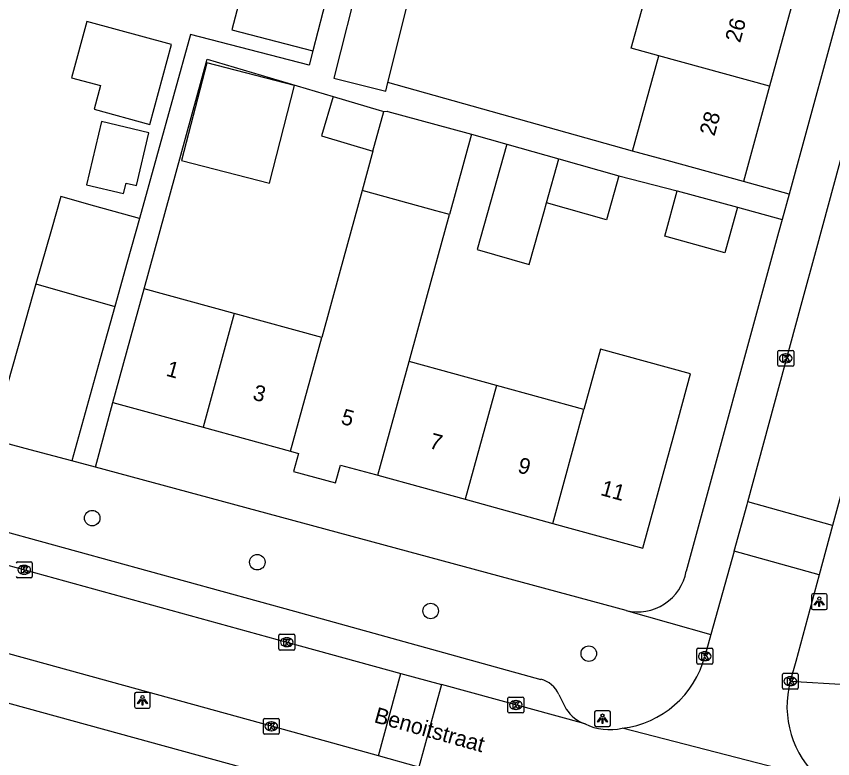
# Model space of a CAD drawing. Extents: x 159822 to 160765, y 380693 to 381634.
# Drawn here: x 160250.2 to 160301.9, y 381019.2 to 381066.1 of the extents above; entities that cross this region are included whole.
import ezdxf

# ---------------------------------------------------------------- set-up
doc = ezdxf.new("R2010")
doc.units = 0
for name, color, linetype in [('IMGEO_Boom', 7, 'Continuous'), ('IMGEO_Kolk', 7, 'Continuous'), ('IMGEO_Lichtpunt', 7, 'Continuous'), ('IMGEO_Openbare_ruimte_label', 7, 'Continuous'), ('IMGEO_Pand', 7, 'Continuous'), ('IMGEO_Pand_nummerreeks', 7, 'Continuous'), ('IMGEO_Rijbaan_lokaal_open', 7, 'Continuous'), ('IMGEO_Voetpad_open', 7, 'Continuous')]:
    doc.layers.add(name, color=color, linetype=linetype)

msp = doc.modelspace()

# ---------------------------------------------------------------- linework, layer by layer
at = {"layer": 'IMGEO_Boom'}
for centre in [(160255.039, 381034.397), (160265.483, 381031.606), (160276.45, 381028.521), (160286.454, 381025.822)]:
    msp.add_circle(centre, 0.489, dxfattribs=at)
at = {"layer": 'IMGEO_Kolk'}
for p, q in [((160298.416, 381044.081), (160298.416, 381044.933)), ((160298.491, 381045.007), (160299.343, 381045.007)), ((160298.904, 381044.787), (160298.929, 381044.787)), ((160299.417, 381044.933), (160299.417, 381044.081)), ((160298.927, 381044.227), (160298.902, 381044.227)), ((160299.343, 381044.007), (160298.491, 381044.007)), ((160250.311, 381031.625), (160251.163, 381031.625)), ((160250.724, 381031.405), (160250.749, 381031.405)), ((160251.237, 381031.551), (160251.237, 381030.699)), ((160250.747, 381030.845), (160250.722, 381030.845)), ((160251.163, 381030.625), (160250.311, 381030.625)), ((160266.849, 381026.121), (160266.849, 381026.973)), ((160266.924, 381027.047), (160267.776, 381027.047)), ((160267.337, 381026.827), (160267.362, 381026.827)), ((160267.85, 381026.973), (160267.85, 381026.121)), ((160267.36, 381026.267), (160267.335, 381026.267)), ((160293.293, 381025.233), (160293.293, 381026.085)), ((160293.368, 381026.159), (160294.22, 381026.159)), ((160294.294, 381026.085), (160294.294, 381025.233)), ((160267.776, 381026.047), (160266.924, 381026.047)), ((160293.781, 381025.939), (160293.806, 381025.939)), ((160294.22, 381025.159), (160293.368, 381025.159)), ((160293.804, 381025.379), (160293.779, 381025.379)), ((160298.779, 381024.577), (160299.631, 381024.577)), ((160298.704, 381023.651), (160298.704, 381024.503)), ((160299.192, 381024.357), (160299.217, 381024.357)), ((160299.705, 381024.503), (160299.705, 381023.651)), ((160299.631, 381023.577), (160298.779, 381023.577)), ((160299.215, 381023.797), (160299.19, 381023.797)), ((160281.339, 381022.15), (160281.339, 381023.002)), ((160281.414, 381023.076), (160282.266, 381023.076)), ((160282.34, 381023.002), (160282.34, 381022.15)), ((160281.827, 381022.856), (160281.852, 381022.856)), ((160282.266, 381022.076), (160281.414, 381022.076)), ((160281.85, 381022.296), (160281.825, 381022.296)), ((160265.867, 381020.8), (160265.867, 381021.652)), ((160265.942, 381021.726), (160266.794, 381021.726)), ((160266.355, 381021.506), (160266.38, 381021.506)), ((160266.868, 381021.652), (160266.868, 381020.8)), ((160266.378, 381020.946), (160266.353, 381020.946)), ((160266.794, 381020.726), (160265.942, 381020.726))]:
    msp.add_line(p, q, dxfattribs=at)
for points in [[(160298.416, 381044.081), (160298.416, 381044.933)], [(160298.491, 381045.007), (160299.343, 381045.007)], [(160298.737, 381044.707), (160298.86, 381044.707), (160298.86, 381044.556), (160298.99, 381044.707), (160299.154, 381044.707), (160299.008, 381044.556), (160299.161, 381044.307), (160299.009, 381044.307), (160298.924, 381044.471), (160298.86, 381044.404), (160298.86, 381044.307), (160298.737, 381044.307), (160298.737, 381044.707)], [(160299.417, 381044.933), (160299.417, 381044.081)], [(160299.343, 381044.007), (160298.491, 381044.007)], [(160250.311, 381031.625), (160251.163, 381031.625)], [(160250.557, 381031.325), (160250.68, 381031.325), (160250.68, 381031.174), (160250.81, 381031.325), (160250.974, 381031.325), (160250.828, 381031.174), (160250.981, 381030.925), (160250.829, 381030.925), (160250.744, 381031.089), (160250.68, 381031.022), (160250.68, 381030.925), (160250.557, 381030.925), (160250.557, 381031.325)], [(160251.237, 381031.551), (160251.237, 381030.699)], [(160251.163, 381030.625), (160250.311, 381030.625)], [(160266.849, 381026.121), (160266.849, 381026.973)], [(160266.924, 381027.047), (160267.776, 381027.047)], [(160267.17, 381026.747), (160267.293, 381026.747), (160267.293, 381026.596), (160267.423, 381026.747), (160267.587, 381026.747), (160267.441, 381026.596), (160267.594, 381026.347), (160267.442, 381026.347), (160267.357, 381026.511), (160267.293, 381026.444), (160267.293, 381026.347), (160267.17, 381026.347), (160267.17, 381026.747)], [(160267.85, 381026.973), (160267.85, 381026.121)], [(160293.293, 381025.233), (160293.293, 381026.085)], [(160293.368, 381026.159), (160294.22, 381026.159)], [(160294.294, 381026.085), (160294.294, 381025.233)], [(160267.776, 381026.047), (160266.924, 381026.047)], [(160293.614, 381025.859), (160293.737, 381025.859), (160293.737, 381025.708), (160293.867, 381025.859), (160294.031, 381025.859), (160293.885, 381025.708), (160294.038, 381025.459), (160293.886, 381025.459), (160293.801, 381025.623), (160293.737, 381025.556), (160293.737, 381025.459), (160293.614, 381025.459), (160293.614, 381025.859)], [(160294.22, 381025.159), (160293.368, 381025.159)], [(160298.779, 381024.577), (160299.631, 381024.577)], [(160298.704, 381023.651), (160298.704, 381024.503)], [(160299.025, 381024.277), (160299.148, 381024.277), (160299.148, 381024.126), (160299.278, 381024.277), (160299.442, 381024.277), (160299.296, 381024.126), (160299.449, 381023.877), (160299.297, 381023.877), (160299.212, 381024.041), (160299.148, 381023.974), (160299.148, 381023.877), (160299.025, 381023.877), (160299.025, 381024.277)], [(160299.705, 381024.503), (160299.705, 381023.651)], [(160299.631, 381023.577), (160298.779, 381023.577)], [(160281.339, 381022.15), (160281.339, 381023.002)], [(160281.414, 381023.076), (160282.266, 381023.076)], [(160282.34, 381023.002), (160282.34, 381022.15)], [(160281.66, 381022.776), (160281.783, 381022.776), (160281.783, 381022.625), (160281.913, 381022.776), (160282.077, 381022.776), (160281.931, 381022.625), (160282.084, 381022.376), (160281.932, 381022.376), (160281.847, 381022.54), (160281.783, 381022.473), (160281.783, 381022.376), (160281.66, 381022.376), (160281.66, 381022.776)], [(160282.266, 381022.076), (160281.414, 381022.076)], [(160265.867, 381020.8), (160265.867, 381021.652)], [(160265.942, 381021.726), (160266.794, 381021.726)], [(160266.868, 381021.652), (160266.868, 381020.8)], [(160266.188, 381021.426), (160266.311, 381021.426), (160266.311, 381021.275), (160266.441, 381021.426), (160266.605, 381021.426), (160266.459, 381021.275), (160266.612, 381021.026), (160266.46, 381021.026), (160266.375, 381021.19), (160266.311, 381021.123), (160266.311, 381021.026), (160266.188, 381021.026), (160266.188, 381021.426)], [(160266.794, 381020.726), (160265.942, 381020.726)]]:
    msp.add_lwpolyline(points, dxfattribs=at)
for centre, start, end in [((160298.493, 381044.931), 91.552, 178.448), ((160298.493, 381044.931), 91.552, 178.448), ((160299.341, 381044.931), 1.552, 88.448), ((160299.341, 381044.931), 1.552, 88.448), ((160298.493, 381044.083), 181.552, 268.448), ((160298.493, 381044.083), 181.552, 268.448), ((160299.341, 381044.083), 271.552, 358.448), ((160299.341, 381044.083), 271.552, 358.448), ((160250.313, 381031.549), 91.552, 178.448), ((160250.313, 381031.549), 91.552, 178.448), ((160251.161, 381031.549), 1.552, 88.448), ((160251.161, 381031.549), 1.552, 88.448), ((160250.313, 381030.701), 181.552, 268.448), ((160250.313, 381030.701), 181.552, 268.448), ((160251.161, 381030.701), 271.552, 358.448), ((160251.161, 381030.701), 271.552, 358.448), ((160266.926, 381026.971), 91.552, 178.448), ((160266.926, 381026.971), 91.552, 178.448), ((160267.774, 381026.971), 1.552, 88.448), ((160267.774, 381026.971), 1.552, 88.448), ((160266.926, 381026.123), 181.552, 268.448), ((160266.926, 381026.123), 181.552, 268.448), ((160267.774, 381026.123), 271.552, 358.448), ((160267.774, 381026.123), 271.552, 358.448), ((160293.37, 381026.083), 91.552, 178.448), ((160293.37, 381026.083), 91.552, 178.448), ((160294.218, 381026.083), 1.552, 88.448), ((160294.218, 381026.083), 1.552, 88.448), ((160293.37, 381025.235), 181.552, 268.448), ((160293.37, 381025.235), 181.552, 268.448), ((160294.218, 381025.235), 271.552, 358.448), ((160294.218, 381025.235), 271.552, 358.448), ((160298.781, 381024.501), 91.552, 178.448), ((160298.781, 381024.501), 91.552, 178.448), ((160299.629, 381024.501), 1.552, 88.448), ((160299.629, 381024.501), 1.552, 88.448), ((160298.781, 381023.653), 181.552, 268.448), ((160298.781, 381023.653), 181.552, 268.448), ((160299.629, 381023.653), 271.552, 358.448), ((160299.629, 381023.653), 271.552, 358.448), ((160281.416, 381023), 91.552, 178.448), ((160281.416, 381023), 91.552, 178.448), ((160282.264, 381023), 1.552, 88.448), ((160282.264, 381023), 1.552, 88.448), ((160281.416, 381022.152), 181.552, 268.448), ((160281.416, 381022.152), 181.552, 268.448), ((160282.264, 381022.152), 271.552, 358.448), ((160282.264, 381022.152), 271.552, 358.448), ((160265.944, 381021.65), 91.552, 178.448), ((160265.944, 381021.65), 91.552, 178.448), ((160266.792, 381021.65), 1.552, 88.448), ((160266.792, 381021.65), 1.552, 88.448), ((160265.944, 381020.802), 181.552, 268.448), ((160265.944, 381020.802), 181.552, 268.448), ((160266.792, 381020.802), 271.552, 358.448), ((160266.792, 381020.802), 271.552, 358.448)]:
    msp.add_arc(centre, 0.0765, start, end, dxfattribs=at)
for centre, major_axis, ratio, start_param, end_param in [((160298.903, 381044.507), (-0.387, 0.002), 0.722429, 4.712389, 7.853982), ((160298.928, 381044.507), (-0.39, 0.002), 0.717154, 1.570796, 4.712389), ((160250.723, 381031.125), (-0.387, 0.002), 0.722429, 4.712389, 7.853982), ((160250.748, 381031.125), (-0.39, 0.002), 0.717154, 1.570796, 4.712389), ((160267.336, 381026.547), (-0.387, 0.002), 0.722429, 4.712389, 7.853982), ((160267.361, 381026.547), (-0.39, 0.002), 0.717154, 1.570796, 4.712389), ((160293.78, 381025.659), (-0.387, 0.002), 0.722429, 4.712389, 7.853982), ((160293.805, 381025.659), (-0.39, 0.002), 0.717154, 1.570796, 4.712389), ((160299.191, 381024.077), (-0.387, 0.002), 0.722429, 4.712389, 7.853982), ((160299.216, 381024.077), (-0.39, 0.002), 0.717154, 1.570796, 4.712389), ((160281.826, 381022.576), (-0.387, 0.002), 0.722429, 4.712389, 7.853982), ((160281.851, 381022.576), (-0.39, 0.002), 0.717154, 1.570796, 4.712389), ((160266.354, 381021.226), (-0.387, 0.002), 0.722429, 4.712389, 7.853982), ((160266.379, 381021.226), (-0.39, 0.002), 0.717154, 1.570796, 4.712389)]:
    msp.add_ellipse(centre, major_axis=major_axis, ratio=ratio, start_param=start_param, end_param=end_param, dxfattribs=at)
at = {"layer": 'IMGEO_Lichtpunt'}
for p, q in [((160300.536, 381029.509), (160300.536, 381028.702)), ((160300.536, 381029.509), (160300.536, 381028.702)), ((160301.438, 381029.604), (160300.63, 381029.604)), ((160301.438, 381029.604), (160300.63, 381029.604)), ((160301.532, 381028.702), (160301.532, 381029.509)), ((160301.532, 381028.702), (160301.532, 381029.509)), ((160300.63, 381028.608), (160301.438, 381028.608)), ((160300.63, 381028.608), (160301.438, 381028.608)), ((160257.718, 381023.276), (160257.718, 381022.469)), ((160257.718, 381023.276), (160257.718, 381022.469)), ((160258.62, 381023.371), (160257.812, 381023.371)), ((160258.62, 381023.371), (160257.812, 381023.371)), ((160258.714, 381022.469), (160258.714, 381023.276)), ((160258.714, 381022.469), (160258.714, 381023.276)), ((160257.812, 381022.375), (160258.62, 381022.375)), ((160257.812, 381022.375), (160258.62, 381022.375)), ((160286.825, 381022.112), (160286.825, 381021.305)), ((160286.825, 381022.112), (160286.825, 381021.305)), ((160287.727, 381022.207), (160286.919, 381022.207)), ((160287.727, 381022.207), (160286.919, 381022.207)), ((160287.821, 381021.305), (160287.821, 381022.112)), ((160287.821, 381021.305), (160287.821, 381022.112)), ((160286.919, 381021.211), (160287.727, 381021.211)), ((160286.919, 381021.211), (160287.727, 381021.211))]:
    msp.add_line(p, q, dxfattribs=at)
for points in [[(160300.91, 381029.173), (160300.949, 381029.145), (160300.761, 381028.883), (160300.723, 381028.91), (160300.91, 381029.173)], [(160301.012, 381029.125), (160301.059, 381029.125), (160301.059, 381028.803), (160301.012, 381028.803), (160301.012, 381029.125)], [(160301.122, 381029.145), (160301.16, 381029.172), (160301.347, 381028.91), (160301.308, 381028.882), (160301.122, 381029.145)], [(160258.092, 381022.94), (160258.131, 381022.912), (160257.943, 381022.65), (160257.905, 381022.677), (160258.092, 381022.94)], [(160258.194, 381022.892), (160258.241, 381022.892), (160258.241, 381022.57), (160258.194, 381022.57), (160258.194, 381022.892)], [(160258.304, 381022.912), (160258.342, 381022.939), (160258.529, 381022.677), (160258.49, 381022.649), (160258.304, 381022.912)], [(160287.199, 381021.776), (160287.238, 381021.748), (160287.05, 381021.486), (160287.012, 381021.513), (160287.199, 381021.776)], [(160287.301, 381021.728), (160287.348, 381021.728), (160287.348, 381021.406), (160287.301, 381021.406), (160287.301, 381021.728)], [(160287.411, 381021.748), (160287.449, 381021.775), (160287.636, 381021.513), (160287.597, 381021.485), (160287.411, 381021.748)]]:
    msp.add_lwpolyline(points, dxfattribs=at)
for centre in [(160301.035, 381029.307), (160258.217, 381023.074), (160287.324, 381021.91)]:
    msp.add_circle(centre, 0.0994, dxfattribs=at)
for centre, start, end in [((160300.63, 381029.509), 90, 180), ((160300.63, 381029.509), 90, 180), ((160301.438, 381029.509), 0, 90), ((160301.438, 381029.509), 0, 90), ((160300.63, 381028.702), 180, 270), ((160300.63, 381028.702), 180, 270), ((160301.438, 381028.702), 270, 0), ((160301.438, 381028.702), 270, 360), ((160257.812, 381023.276), 90, 180), ((160257.812, 381023.276), 90, 180), ((160258.62, 381023.276), 0, 90), ((160258.62, 381023.276), 0, 90), ((160257.812, 381022.469), 180, 270), ((160257.812, 381022.469), 180, 270), ((160258.62, 381022.469), 270, 0), ((160258.62, 381022.469), 270, 360), ((160286.919, 381022.112), 90, 180), ((160286.919, 381022.112), 90, 180), ((160287.727, 381022.112), 0, 90), ((160287.727, 381022.112), 0, 90), ((160286.919, 381021.305), 180, 270), ((160286.919, 381021.305), 180, 270), ((160287.727, 381021.305), 270, 0), ((160287.727, 381021.305), 270, 360)]:
    msp.add_arc(centre, 0.0946, start, end, dxfattribs=at)
at = {"layer": 'IMGEO_Pand'}
for points in [[(160290.882, 381063.641), (160289.142, 381064.119), (160290.75, 381069.971), (160292.49, 381069.493)], [(160264.647, 381069.157), (160264.018, 381069.345), (160263.649, 381067.936), (160264.497, 381067.702), (160263.869, 381065.283), (160268.992, 381063.951)], [(160271.985, 381068.835), (160270.332, 381062.225), (160273.604, 381061.407), (160273.739, 381061.948)], [(160273.739, 381061.948), (160275.238, 381067.942)], [(160269.943, 381067.639), (160268.992, 381063.951)], [(160299.5, 381067.568), (160297.891, 381061.715)], [(160260.059, 381064.358), (160254.705, 381065.819), (160253.733, 381062.253), (160255.563, 381061.754), (160255.157, 381060.266), (160258.681, 381059.305), (160260.059, 381064.358)], [(160289.226, 381057.613), (160290.882, 381063.641)], [(160297.891, 381061.715), (160290.882, 381063.641)], [(160260.686, 381057.015), (160266.248, 381055.581), (160267.842, 381061.762), (160262.28, 381063.196), (160260.686, 381057.015)], [(160297.891, 381061.715), (160296.235, 381055.687)], [(160270.289, 381061.073), (160269.55, 381058.573), (160272.797, 381057.615)], [(160270.289, 381061.073), (160273.201, 381060.212), (160273.487, 381060.127)], [(160272.797, 381057.615), (160273.487, 381060.127)], [(160273.487, 381060.127), (160273.703, 381060.137), (160273.741, 381060.126), (160278.806, 381058.738), (160279.036, 381058.675)], [(160255.621, 381059.477), (160254.675, 381055.477), (160257.021, 381054.922), (160257.179, 381055.589), (160257.84, 381055.433), (160258.628, 381058.765), (160255.621, 381059.477)], [(160279.036, 381058.675), (160277.642, 381053.601)], [(160272.797, 381057.615), (160272.11, 381055.116)], [(160281.274, 381058.06), (160279.382, 381051.38), (160282.687, 381050.444), (160283.633, 381053.784), (160283.783, 381054.332)], [(160281.274, 381058.06), (160284.552, 381057.132)], [(160296.235, 381055.687), (160291.414, 381057.012), (160289.226, 381057.613)], [(160283.783, 381054.332), (160284.552, 381057.132)], [(160284.552, 381057.132), (160288.356, 381056.055)], [(160288.356, 381056.055), (160287.566, 381053.262), (160283.783, 381054.332)], [(160272.11, 381055.116), (160270.659, 381049.834), (160269.557, 381045.823)], [(160277.642, 381053.601), (160277.415, 381053.663), (160276.78, 381053.837), (160272.351, 381055.05), (160272.11, 381055.116)], [(160295.856, 381054.058), (160295.067, 381051.184), (160291.257, 381052.231), (160292.047, 381055.105)], [(160292.047, 381055.105), (160295.856, 381054.058)], [(160258.02, 381053.345), (160255.204, 381054.13), (160253.047, 381054.732), (160252.457, 381052.661), (160251.474, 381049.214)], [(160275.088, 381044.304), (160276.19, 381048.315), (160277.642, 381053.601)], [(160258.02, 381053.345), (160257.249, 381050.579), (160256.469, 381047.783)], [(160251.474, 381049.214), (160250.62, 381046.217), (160248.67, 381039.377)], [(160251.474, 381049.214), (160256.469, 381047.783)], [(160256.352, 381041.707), (160257.677, 381046.529), (160258.33, 381048.907)], [(160264.026, 381047.342), (160258.33, 381048.907)], [(160256.469, 381047.783), (160255.546, 381044.474), (160253.745, 381038.017)], [(160264.026, 381047.342), (160262.049, 381040.142)], [(160269.557, 381045.823), (160264.026, 381047.342)], [(160267.579, 381038.623), (160269.557, 381045.823)], [(160284.171, 381034.065), (160289.87, 381032.5), (160291.848, 381039.7), (160292.895, 381043.513), (160287.195, 381045.079), (160286.148, 381041.265)], [(160273.11, 381037.104), (160275.088, 381044.304)], [(160280.618, 381042.784), (160275.088, 381044.304)], [(160280.618, 381042.784), (160278.641, 381035.584)], [(160286.148, 381041.265), (160280.618, 381042.784)], [(160256.352, 381041.707), (160262.049, 381040.142)], [(160284.171, 381034.065), (160286.148, 381041.265)], [(160262.049, 381040.142), (160267.579, 381038.623)], [(160253.745, 381038.017), (160251.114, 381038.722), (160248.67, 381039.377)], [(160267.579, 381038.623), (160268.087, 381038.483), (160267.775, 381037.347), (160270.427, 381036.619), (160270.739, 381037.755), (160272.957, 381037.146), (160273.11, 381037.104)], [(160273.11, 381037.104), (160278.641, 381035.584)], [(160278.641, 381035.584), (160284.171, 381034.065)]]:
    msp.add_lwpolyline(points, dxfattribs=at)
at = {"layer": 'IMGEO_Rijbaan_lokaal_open'}
for points in [[(160296.519, 381035.423), (160299.893, 381047.861), (160300.877, 381051.49), (160313.515, 381098.085)], [(160318.934, 381096.61), (160301.881, 381033.927)], [(160231.237, 381036.497), (160267.35, 381026.546), (160274.572, 381024.566)], [(160295.649, 381032.302), (160296.475, 381035.26), (160296.519, 381035.423)], [(160301.881, 381033.927), (160296.519, 381035.423)], [(160301.881, 381033.927), (160301.031, 381030.8)], [(160295.649, 381032.302), (160294.18, 381027.04)], [(160301.031, 381030.8), (160295.649, 381032.302)], [(160273.143, 381019.356), (160266.372, 381021.226), (160229.825, 381031.293)], [(160301.031, 381030.8), (160299.544, 381025.33), (160299.204, 381024.077)], [(160294.18, 381027.04), (160293.795, 381025.659)], [(160273.143, 381019.356), (160274.572, 381024.566)], [(160274.572, 381024.566), (160277.137, 381023.863)], [(160277.137, 381023.863), (160275.707, 381018.648)], [(160286.218, 381021.373), (160277.137, 381023.863)], [(160301.074, 381017.892), (160288.567, 381021.104)], [(160275.707, 381018.648), (160273.143, 381019.356)]]:
    msp.add_lwpolyline(points, dxfattribs=at)
for centre, radius, start, end in [((160287.845, 381027.21), 6.149, 276.7423, 345.387), ((160305.1, 381022.484), 6.107, 164.8834, 228.7614), ((160287.771, 381024.543), 3.53, 243.899, 283.0353)]:
    msp.add_arc(centre, radius, start, end, dxfattribs=at)
at = {"layer": 'IMGEO_Voetpad_open'}
for points in [[(160309.076, 381091.342), (160299.133, 381054.896)], [(160268.992, 381063.951), (160268.76, 381063.052), (160261.265, 381064.985), (160258.02, 381053.345)], [(160258.33, 381048.907), (160262.318, 381063.43), (160270.289, 381061.073)], [(160289.226, 381057.613), (160273.739, 381061.948)], [(160279.036, 381058.675), (160281.274, 381058.06)], [(160288.356, 381056.055), (160292.047, 381055.105)], [(160299.133, 381054.896), (160296.235, 381055.687)], [(160299.133, 381054.896), (160298.693, 381053.284)], [(160295.856, 381054.058), (160298.693, 381053.284)], [(160298.693, 381053.284), (160298.467, 381052.456), (160292.622, 381031.031)], [(160255.246, 381037.612), (160256.352, 381041.707)], [(160231.031, 381038.636), (160267.84, 381028.499), (160283.414, 381024.197)], [(160255.246, 381037.612), (160253.745, 381038.017)], [(160288.809, 381028.544), (160255.246, 381037.612)], [(160227.232, 381028.872), (160273.402, 381016.188)], [(160288.809, 381028.544), (160294.18, 381027.04)], [(160299.204, 381024.077), (160306.239, 381023.664)], [(160284.549, 381023.241), (160285.031, 381022.315)]]:
    msp.add_lwpolyline(points, dxfattribs=at)
for centre, radius, start, end in [((160289.52, 381031.621), 3.158, 256.9953, 349.2328), ((160283.058, 381022.622), 1.615, 22.5332, 77.2525), ((160287.002, 381023.58), 2.343, 212.6936, 250.4356)]:
    msp.add_arc(centre, radius, start, end, dxfattribs=at)

# ---------------------------------------------------------------- texts
at = {"layer": 'IMGEO_Openbare_ruimte_label'}
msp.add_text('Benoitstraat', height=1, rotation=344.3931, dxfattribs=at).set_placement((160272.815, 381021.492))
at = {"layer": 'IMGEO_Pand_nummerreeks'}
for s, rotation, p in [('26', 74.6335, (160296.022, 381064.425)), ('28', 74.6355, (160294.4, 381058.516)), ('1', 344.6404, (160259.657, 381043.413)), ('3', 344.6404, (160265.134, 381041.909)), ('5', 344.639, (160270.719, 381040.374)), ('7', 344.6404, (160276.306, 381038.84)), ('9', 344.6404, (160281.893, 381037.305)), ('11', 344.639, (160287.145, 381035.863))]:
    msp.add_text(s, height=1, rotation=rotation, dxfattribs=at).set_placement(p)

doc.saveas('drawing.dxf')
